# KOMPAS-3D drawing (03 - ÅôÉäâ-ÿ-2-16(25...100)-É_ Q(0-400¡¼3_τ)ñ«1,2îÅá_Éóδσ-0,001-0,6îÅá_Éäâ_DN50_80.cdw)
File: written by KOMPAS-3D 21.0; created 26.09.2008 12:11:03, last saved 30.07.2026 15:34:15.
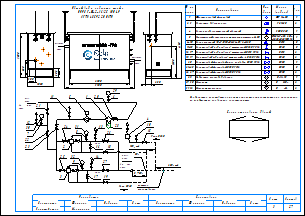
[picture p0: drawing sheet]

Sheets 1-2: A3, landscape

Document properties: Наименование: Макро:21; Автор: RaskoAdmin; Форматы листов документа: 2xA3; Полное имя файла: \\ur38nt01\Departments\КТО\КБ ПУРДГ\Заявки\Прайс-лист на типовые шкафы ГРПШ\ПУРДГ_стандарт_30_04_2026\ПУРДГ с РДГ(Н, В)\ПУРДГ-Ш-2-16(25...100)-Р_ Q(0-400нм3_ч)до1,2МПа_Рвых-0,001-0,6МПа_РДГ_DN50_80.cdw

Title block, sheet 1: Наименование: Пункт учета газа / ПУГ-Ш-400-Р / ЛГТИ.485922.001ТУ; designation: ЛГТИ.03.4411141; sheet number: 1; Количество листов документа: 2; organisation: ООО "ЭЛЬСТЕР Газэлектроника"; Форматы листов документа: A3; stored path: C:\Рабочие документы\Компас\ПУГ\Схема.cdw; Разработал: Устинов; Проверил: Кошкин; Утвердил: Кошкин
Title block, sheet 2: sheet number: 2; stored path: D:\Рабочие документы\Заявки\ПУРДГ\ПУРДГ-ШУЭО-2-100-Р 4411220.cdw; designation, second copy: ЛГТИ.03.4411141-

Views: Вид 1, Вид 2
Referenced files: wcvoit.frw
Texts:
  Normal
  № на
  схеме
  Усл.
  обозн.
  Марка
  (модель)
  Кол.
  Фильтр газовый фланцевый
  ФГ 16-50
  Регулятор давления газа
  РДГ-50
  Клапан предохранительный сбросной
  КПС DN20
  Измерительный комплекс с ротационным счетчиком Ду50
  СГ-ЭК-Р-(0,2...2,0)-
  Кран кнопочный VE-РАСКО-НЗ-1,6-G1/2-М20
  DN15
  Кран шаровой "под приварку" штуцерный DN20 PN16
  DN20
  Кран шаровой "под приварку" штуцерный DN15 PN16
  Кран шаровой "под приварку" штуцерный п/п DN20 PN16
  Кран шаровой фланцевый с мех. приводом DN50 PN16
  Кран шаровой фланцевый DN50 PN16
  Кран шаровой фланцевый DN80 PN16
  DN50
  DN80
  Индикатор перепада давления
  Манометр
  Манометр-напоромер
  Delta 15
  0...     МПа
  0...     кПа
  Общий вид и габариты шкафа
  ПУРДГ-Ш-2-16(25...100)-Р
  Выход газа
  Вход газа
  logo-rasko-ge.png
  DN 1
  местное
  сопротивление
  Римп DN20
  Выход
  газа
  Р=     кПа
  Вход
  Р=       МПа
  PDI
  Схема открывания дверей
  Предприятие изготовитель может заменять комплектующие на аналогичные,
  не ухудшающие заявленных характеристик.
  Должность
  Конструктор
  Фамилия
  Подпись
  Дата
  Согласовано
  Максимкин
  Лист
  Листов
  POLYLINE_STYLE_0.18_RGB_0_0_0
  POLYLINE_STYLE_0.50_RGB_0_0_0
  POLYLINE_STYLE_0.34_RGB_0_0_0
  PHANTOM_RGB_0_0_0_SC_1_THICK_0.18
  K5LT_THIN_RGB_0_0_0_THICK_0.18
  K5LT32769_RGB_0_0_0_THICK_0.18
  K5LT12_RGB_0_0_0_SC_1_THICK_0.18
  K5LT_DASHED_RGB_0_0_0_SC_1_THICK_0.18
  ACISOTGL_RGB_0_0_0_SC_0.8_THICK_0.25
  CONTINUOUS_RGB_0_127_31_THICK_0.3
  CONTINUOUS_RGB_0_0_255_THICK_0.35
  CONTINUOUS_RGB_255_0_0_THICK_0.35
  POLYLINE_STYLE_0.25_RGB_0_0_0
  CONTINUOUS_RGB_0_0_0_THICK_0.5
  POLYLINE_STYLE_0.35_RGB_0_0_255
  CONTINUOUS_RGB_0_0_0_THICK_0.4
  CONTINUOUS_RGB_0_0_0_THICK_0.35
  НЕВИДИМАЯ_RGB_0_0_0_SC_0.3_THICK_0.25
  СONTINUOUS_RGB_0_0_0_THICK_0.25
  ОСЕВАЯ2_RGB_248_153_30_SC_0.3_THICK_0.25
  Без оформления
Dimensions and other numbers on the sheet: 1; 2, 3; 2; 4; 5; 6-10; 11-15; 16, 17; 18, 19; 20; 21-25; 26, 27; 28; 29, 30; 31, 32; 1500; 250; 300; 1050; 550; 305; 2800; 4130; 2000; 3100; 5,,,7DN 1; 7; 30; 12; 21; 22; 23; 11; 6; 29; 24; 31; 8; 13; 26; 18; 10; 15; 25; 32; 9; 3; 14; 27; 19; 16; 17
